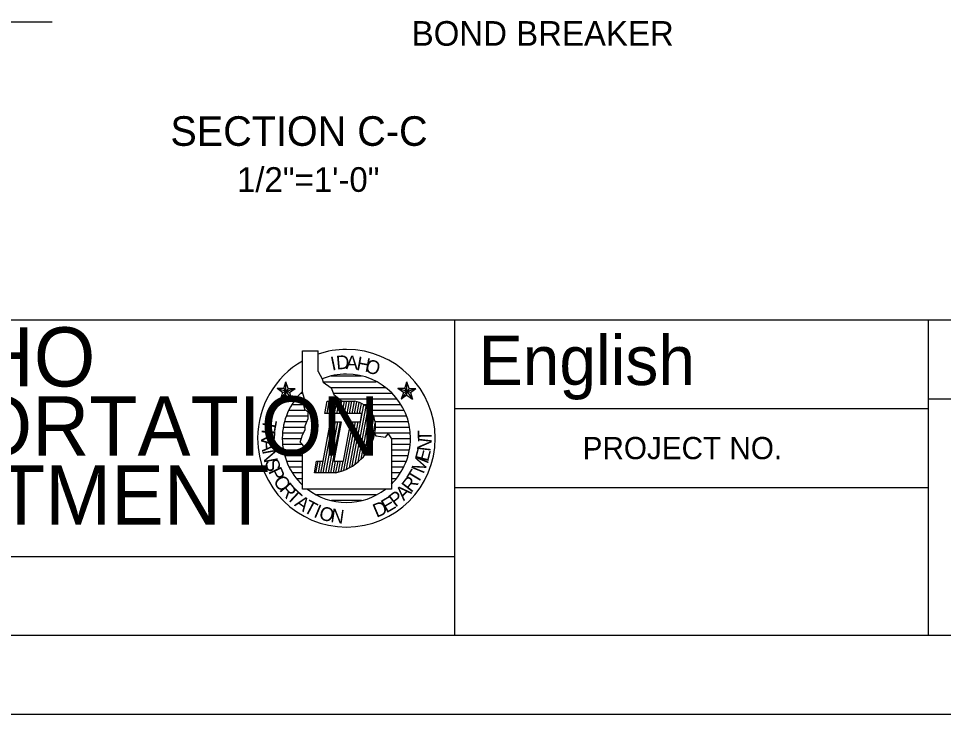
# Model space of a CAD drawing. Extents: x 0 to 68, y 0 to 47.1.
# Drawn here: x 32.97 to 44.69, y 0 to 8.82 of the extents above; entities that cross this region are included whole.
import ezdxf

# ---------------------------------------------------------------- set-up
doc = ezdxf.new("R2010")
doc.units = 0
for name, color, linetype in [('BORDER_ANNO_Cutsheet', 7, 'Continuous'), ('BRDG_ANNO_Anno-Sheet', 7, 'Continuous'), ('BRDG_ANNO_General-Notes', 7, 'Continuous')]:
    doc.layers.add(name, color=color, linetype=linetype)

msp = doc.modelspace()

# ---------------------------------------------------------------- linework, layer by layer
at = {"layer": 'BORDER_ANNO_Cutsheet'}
msp.add_lwpolyline([(0, 44), (68, 44), (68, 0), (0, 0)], close=True, dxfattribs=at)
at = {"layer": 'BRDG_ANNO_Anno-Sheet'}
for p, q in [((3, 5), (38.5, 5)), ((38.5, 1), (38.5, 5)), ((38.5, 5), (67, 5)), ((44.5, 1), (44.5, 5)), ((36.569, 4.085), (36.569, 4.606)), ((36.569, 4.606), (36.766, 4.606)), ((36.766, 4.346), (36.766, 4.606)), ((36.766, 4.346), (36.819, 4.252)), ((36.819, 4.252), (36.829, 4.21)), ((36.93, 4.289), (37.316, 4.289)), ((36.402, 4.08), (36.245, 4.131)), ((36.331, 4.131), (36.245, 4.131)), ((36.315, 4.08), (36.245, 4.131)), ((36.386, 4.131), (36.288, 3.996)), ((36.315, 4.08), (36.474, 4.131)), ((36.331, 4.131), (36.359, 4.214)), ((36.331, 4.131), (36.43, 3.996)), ((36.359, 4.047), (36.359, 4.214)), ((36.386, 4.131), (36.359, 4.214)), ((36.386, 4.131), (36.474, 4.131)), ((36.402, 4.08), (36.474, 4.131)), ((36.829, 4.21), (36.932, 4.138)), ((36.834, 4.216), (37.501, 4.216)), ((36.93, 4.145), (37.614, 4.145)), ((36.932, 4.138), (36.965, 4.054)), ((37.935, 4.08), (37.776, 4.131)), ((37.847, 4.08), (37.776, 4.131)), ((37.864, 4.131), (37.776, 4.131)), ((37.919, 4.131), (37.82, 3.996)), ((37.847, 4.08), (38.005, 4.131)), ((37.864, 4.131), (37.891, 4.214)), ((37.864, 4.131), (37.962, 3.996)), ((37.891, 4.047), (37.891, 4.214)), ((37.919, 4.131), (37.891, 4.214)), ((37.919, 4.131), (38.005, 4.131)), ((37.935, 4.08), (38.005, 4.131)), ((36.315, 4.08), (36.288, 3.996)), ((36.359, 4.047), (36.288, 3.996)), ((36.359, 4.047), (36.43, 3.996)), ((36.402, 4.08), (36.43, 3.996)), ((36.484, 4.001), (36.587, 4.001)), ((36.549, 4.072), (36.572, 4.072)), ((36.589, 4.013), (36.569, 4.085)), ((36.589, 3.95), (36.589, 4.013)), ((36.957, 4.072), (37.701, 4.072)), ((36.965, 4.054), (37.069, 3.971)), ((37.031, 4.001), (37.765, 4.001)), ((37.847, 4.08), (37.82, 3.996)), ((37.891, 4.047), (37.82, 3.996)), ((37.891, 4.047), (37.962, 3.996)), ((37.935, 4.08), (37.962, 3.996)), ((44.5, 4), (60.5, 4)), ((36.434, 3.929), (36.585, 3.929)), ((36.589, 3.897), (36.589, 3.95)), ((36.6, 3.856), (36.589, 3.897)), ((36.85, 3.814), (36.881, 3.971)), ((36.879, 3.814), (36.907, 3.971)), ((36.881, 3.971), (37.225, 3.971)), ((36.91, 3.814), (36.94, 3.971)), ((36.942, 3.814), (36.971, 3.971)), ((36.974, 3.814), (37.004, 3.971)), ((37.005, 3.814), (37.035, 3.971)), ((37.038, 3.814), (37.066, 3.971)), ((37.069, 3.814), (37.099, 3.971)), ((37.101, 3.814), (37.13, 3.971)), ((37.133, 3.814), (37.163, 3.971)), ((37.165, 3.814), (37.194, 3.971)), ((37.196, 3.814), (37.226, 3.971)), ((37.199, 3.149), (37.344, 3.924)), ((37.227, 3.814), (37.256, 3.962)), ((37.235, 3.171), (37.373, 3.904)), ((37.26, 3.814), (37.286, 3.954)), ((37.273, 3.201), (37.399, 3.877)), ((37.291, 3.814), (37.315, 3.94)), ((37.337, 3.929), (37.815, 3.929)), ((38.5, 3.875), (44.5, 3.875)), ((36.362, 3.785), (36.637, 3.785)), ((36.394, 3.856), (36.596, 3.856)), ((36.641, 3.835), (36.6, 3.856)), ((36.62, 3.7), (36.641, 3.751)), ((36.641, 3.782), (36.641, 3.835)), ((36.641, 3.751), (36.641, 3.782)), ((37.322, 3.814), (36.85, 3.814)), ((37.304, 3.71), (37.322, 3.814)), ((37.311, 3.237), (37.425, 3.849)), ((37.351, 3.28), (37.45, 3.812)), ((37.394, 3.337), (37.474, 3.764)), ((37.42, 3.856), (37.855, 3.856)), ((37.465, 3.785), (37.886, 3.785)), ((36.325, 3.641), (36.596, 3.641)), ((36.341, 3.712), (36.623, 3.712)), ((36.6, 3.657), (36.62, 3.7)), ((36.6, 3.606), (36.6, 3.657)), ((36.829, 3.21), (36.922, 3.71)), ((36.832, 3.064), (36.954, 3.71)), ((36.865, 3.064), (36.986, 3.71)), ((36.896, 3.064), (37.017, 3.71)), ((36.922, 3.71), (37.06, 3.71)), ((36.929, 3.064), (37.05, 3.71)), ((37.06, 3.71), (36.966, 3.21)), ((37.087, 3.21), (37.181, 3.71)), ((37.094, 3.095), (37.209, 3.71)), ((37.127, 3.11), (37.24, 3.71)), ((37.163, 3.126), (37.273, 3.71)), ((37.181, 3.71), (37.304, 3.71)), ((37.444, 3.435), (37.491, 3.69)), ((37.489, 3.712), (37.909, 3.712)), ((37.495, 3.641), (37.925, 3.641)), ((36.315, 3.569), (36.581, 3.569)), ((36.557, 3.501), (36.569, 3.544)), ((36.569, 3.544), (36.6, 3.606)), ((37.481, 3.555), (37.496, 3.532)), ((37.485, 3.569), (37.935, 3.569)), ((37.496, 3.532), (37.559, 3.522)), ((37.559, 3.522), (37.621, 3.512)), ((37.621, 3.512), (37.652, 3.554)), ((37.652, 3.554), (37.694, 3.491)), ((36.312, 3.496), (36.555, 3.496)), ((36.316, 3.425), (36.562, 3.425)), ((36.538, 3.45), (36.557, 3.501)), ((36.569, 3.419), (36.538, 3.45)), ((36.589, 3.387), (36.569, 3.419)), ((37.69, 3.496), (37.938, 3.496)), ((37.694, 3.491), (37.694, 2.855)), ((37.695, 3.425), (37.934, 3.425)), ((36.326, 3.353), (36.596, 3.353)), ((36.569, 3.304), (36.6, 3.335)), ((36.569, 2.855), (36.569, 3.304)), ((36.6, 3.366), (36.589, 3.387)), ((36.6, 3.335), (36.6, 3.366)), ((37.694, 3.353), (37.924, 3.353)), ((36.343, 3.281), (36.567, 3.281)), ((36.367, 3.209), (36.565, 3.209)), ((36.719, 3.064), (36.746, 3.21)), ((36.737, 3.064), (36.765, 3.21)), ((36.746, 3.21), (36.829, 3.21)), ((36.77, 3.064), (36.797, 3.21)), ((36.801, 3.064), (36.829, 3.21)), ((36.96, 3.064), (36.987, 3.21)), ((36.966, 3.21), (37.087, 3.21)), ((36.992, 3.065), (37.02, 3.21)), ((37.026, 3.074), (37.051, 3.21)), ((37.06, 3.084), (37.082, 3.21)), ((37.694, 3.281), (37.907, 3.281)), ((37.694, 3.209), (37.883, 3.209)), ((36.399, 3.136), (36.565, 3.136)), ((36.44, 3.065), (36.566, 3.065)), ((36.985, 3.064), (36.719, 3.064)), ((37.694, 3.136), (37.85, 3.136)), ((37.694, 3.065), (37.81, 3.065)), ((36.491, 2.992), (36.565, 2.992)), ((37.694, 2.992), (37.76, 2.992)), ((36.555, 2.921), (36.567, 2.921)), ((37.694, 2.855), (36.569, 2.855)), ((38.5, 2.875), (44.5, 2.875)), ((37.501, 2.782), (36.744, 2.782)), ((37.317, 2.711), (36.935, 2.711)), ((28, 2), (38.5, 2))]:
    msp.add_line(p, q, dxfattribs=at)
msp.add_lwpolyline([(3, 43), (67, 43), (67, 1), (3, 1)], close=True, dxfattribs=at)
for centre, radius, start, end in [((37.125, 3.5), 1.125, 90, 108.596), ((37.125, 3.5), 1.125, 0, 90), ((37.125, 3.5), 1.125, 119.6331, 180), ((37.125, 3.5), 0.813, 90, 112.1452), ((37.125, 3.5), 0.813, 0, 90), ((37.125, 3.5), 0.813, 133.1926, 180), ((37.167, 3.648), 0.328, 343.4981, 79.7362), ((36.87, 3.676), 0.623, 280.6479, 348.7719), ((37.125, 3.5), 1.125, 180, 270), ((37.125, 3.5), 0.813, 180.2644, 226.7946), ((37.125, 3.5), 1.125, 270, 0), ((37.125, 3.5), 0.813, 314.427, 0), ((37.125, 3.5), 0.813, 232.5658, 270), ((37.125, 3.5), 0.813, 270, 307.4536)]:
    msp.add_arc(centre, radius, start, end, dxfattribs=at)
at = {"layer": 'BRDG_ANNO_General-Notes'}
msp.add_line((33.397, 8.77), (32.581, 8.77), dxfattribs=at)

# ---------------------------------------------------------------- texts
at = {"layer": 'BRDG_ANNO_Anno-Sheet'}
for s, height, p in [('IDAHO', 0.75, (30.767, 4.156)), ('English', 0.625, (38.801, 4.174)), ('TRANSPORTATION', 0.75, (28.294, 3.281)), ('PROJECT NO.', 0.28125, (40.118, 3.235)), ('DEPARTMENT', 0.75, (29.239, 2.406))]:
    msp.add_text(s, height=height, dxfattribs=at).set_placement(p)
for s, rotation, p in [('I', 11.9519, (36.944, 4.356)), ('D', 5.2118, (37.002, 4.369)), ('A', 357.8718, (37.114, 4.376)), ('H', 349.6318, (37.244, 4.367)), ('O', 342.1917, (37.349, 4.346)), ('T', 259.4265, (36.076, 3.751)), ('R', 266.0275, (36.053, 3.615)), ('T', 90.4926, (38.204, 3.459)), ('A', 273.764, (36.046, 3.481)), ('N', 83.1932, (38.19, 3.326)), ('N', 280.3758, (36.057, 3.342)), ('E', 75.6105, (38.159, 3.194)), ('S', 287.9279, (36.086, 3.208)), ('M', 67.7139, (38.101, 3.041)), ('P', 295.4976, (36.131, 3.081)), ('T', 59.0362, (38.027, 2.91)), ('O', 302.6446, (36.191, 2.96)), ('R', 309.9079, (36.267, 2.845)), ('R', 52.3344, (37.947, 2.802)), ('T', 317.1211, (36.355, 2.742)), ('P', 37.6656, (37.746, 2.619)), ('A', 45, (37.851, 2.701)), ('A', 324.6375, (36.456, 2.651)), ('T', 331.7503, (36.569, 2.574)), ('E', 30.5476, (37.631, 2.547)), ('I', 337.0213, (36.699, 2.507)), ('O', 343.3287, (36.765, 2.481)), ('N', 351.6598, (36.917, 2.44)), ('D', 22.9887, (37.506, 2.491))]:
    msp.add_text(s, height=0.174, rotation=rotation, dxfattribs=at).set_placement(p)
at = {"layer": 'BRDG_ANNO_General-Notes'}
for s, height, p in [('BOND BREAKER', 0.3125, (37.952, 8.473)), ('SECTION C-C', 0.375, (34.894, 7.205)), ('1/2"=1\'-0"', 0.3125, (35.738, 6.622))]:
    msp.add_text(s, height=height, dxfattribs=at).set_placement(p)

doc.saveas('drawing.dxf')
